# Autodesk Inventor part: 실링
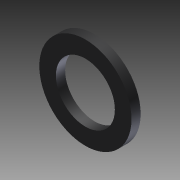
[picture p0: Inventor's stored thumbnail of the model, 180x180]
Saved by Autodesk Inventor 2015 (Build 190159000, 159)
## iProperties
Created: 2024-12
Part Number: 실링
Material: 일반
Document SubType Name: Modeling
Designer: 10401
Density: 1 g/cm^3
Appearance: 기본값
Author: 10401
Author: jhkim
Creation Date: 2024-11-28
Sending System: Autodesk Inventor 2025
Preprocessor: ST-DEVELOPER v20
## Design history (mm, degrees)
node "실링1"
node "솔리드1"
node "기준1"
